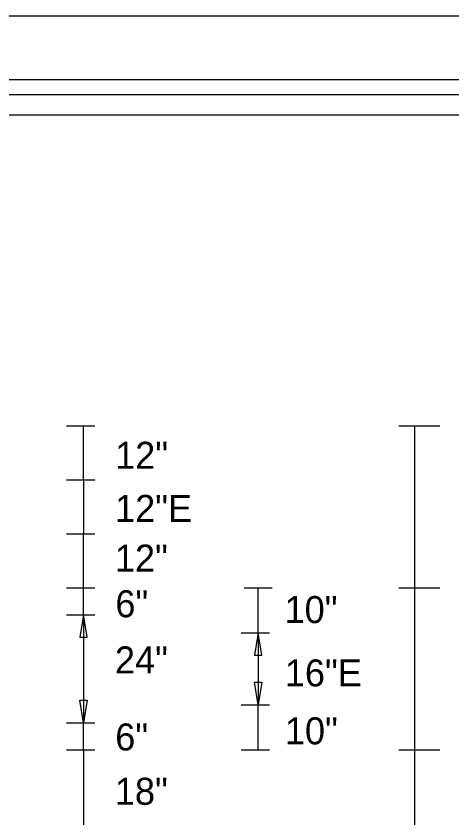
# Model space of a CAD drawing. Extents: x 119523 to 121850, y -23542 to -19972.
# Drawn here: x 121482.7 to 121579.6, y -22205.9 to -22027.7 of the extents above; entities that cross this region are included whole.
import ezdxf

# ---------------------------------------------------------------- set-up
doc = ezdxf.new("R2010")
doc.units = 0
for name, color, linetype in [('GSDims', 7, 'Continuous'), ('PlotBorder_dp', 7, 'Continuous'), ('SheetBorder_dp', 7, 'Continuous'), ('SheetLinesMisc2_dp', 7, 'Continuous')]:
    doc.layers.add(name, color=color, linetype=linetype)

msp = doc.modelspace()

# ---------------------------------------------------------------- linework, layer by layer
at = {"layer": 'GSDims'}
for p, q in [((121493.98, -22118.76), (121500.23, -22118.76)), ((121493.98, -22118.76), (121493.98, -22118.76)), ((121497.73, -22130.76), (121497.73, -22118.76)), ((121567.86, -22118.76), (121576.97, -22118.76)), ((121571.35, -22118.76), (121571.35, -22154.76)), ((121493.98, -22130.76), (121500.23, -22130.76)), ((121493.98, -22130.76), (121500.23, -22130.76)), ((121497.73, -22130.76), (121497.73, -22142.76)), ((121493.98, -22142.76), (121500.23, -22142.76)), ((121493.98, -22142.76), (121500.23, -22142.76)), ((121497.73, -22154.76), (121497.73, -22142.76)), ((121493.98, -22154.76), (121500.23, -22154.76)), ((121493.98, -22154.76), (121500.23, -22154.76)), ((121497.73, -22160.76), (121497.73, -22154.76)), ((121533.43, -22154.76), (121539.68, -22154.76)), ((121536.56, -22164.76), (121536.56, -22154.76)), ((121567.86, -22154.76), (121576.97, -22154.76)), ((121571.35, -22154.76), (121571.35, -22304.76)), ((121493.98, -22160.76), (121500.23, -22160.76)), ((121497.73, -22160.76), (121497.73, -22184.76)), ((121532.81, -22164.76), (121539.06, -22164.76)), ((121532.81, -22164.76), (121539.06, -22164.76)), ((121536.56, -22164.76), (121536.56, -22180.76)), ((121532.81, -22180.76), (121539.06, -22180.76)), ((121532.81, -22180.76), (121539.06, -22180.76)), ((121536.56, -22190.76), (121536.56, -22180.76)), ((121493.98, -22184.76), (121500.23, -22184.76)), ((121493.98, -22184.76), (121500.23, -22184.76)), ((121497.73, -22190.76), (121497.73, -22184.76)), ((121493.98, -22190.76), (121500.23, -22190.76)), ((121497.73, -22190.76), (121497.73, -22268.76)), ((121532.81, -22190.76), (121539.06, -22190.76)), ((121567.86, -22190.76), (121576.97, -22190.76))]:
    msp.add_line(p, q, dxfattribs=at)
for points in [[(121497.73, -22160.76), (121496.89, -22165.76), (121498.56, -22165.76)], [(121536.56, -22164.76), (121535.72, -22169.76), (121537.39, -22169.76)], [(121536.56, -22180.76), (121535.72, -22175.76), (121537.39, -22175.76)], [(121497.73, -22184.76), (121496.89, -22179.76), (121498.56, -22179.76)]]:
    msp.add_lwpolyline(points, close=True, dxfattribs=at)
at = {"layer": 'PlotBorder_dp'}
msp.add_lwpolyline([(119522.87, -23522.86), (121850.2, -23522.86), (121850.2, -22027.72), (119522.87, -22027.72)], close=True, dxfattribs=at)
at = {"layer": 'SheetBorder_dp'}
msp.add_line((119600.45, -22041.83), (121772.62, -22041.83), dxfattribs=at)
at = {"layer": 'SheetLinesMisc2_dp'}
for p, q in [((119604.34, -22045.17), (121770.65, -22045.17)), ((121023.51, -22049.66), (121760.29, -22049.66))]:
    msp.add_line(p, q, dxfattribs=at)

# ---------------------------------------------------------------- texts
at = {"layer": 'GSDims'}
for s, p in [('12"', (121504.76, -22128.33)), ('12"E', (121504.74, -22140.13)), ('12"', (121504.71, -22151.18)), ('6"', (121504.81, -22161.32)), ('10"', (121542.43, -22162.61)), ('24"', (121504.72, -22173.81)), ('16"E', (121542.49, -22176.69)), ('10"', (121542.5, -22189.56)), ('6"', (121504.78, -22190.92)), ('18"', (121504.7, -22203))]:
    msp.add_text(s, height=6, rotation=360, dxfattribs=at).set_placement(p)

doc.saveas('drawing.dxf')
